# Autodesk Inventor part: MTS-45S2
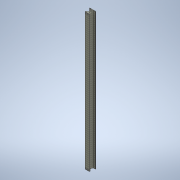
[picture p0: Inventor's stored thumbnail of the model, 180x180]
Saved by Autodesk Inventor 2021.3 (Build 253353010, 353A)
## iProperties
Created: 2021-11
Part Number: MTS-45S2
Material: Concrete, Precast
Document SubType Name: Modeling
Designer: u1426
Density: 2.40731 g/cm^3
Appearance: Smooth Precast Structural
Author: u1426
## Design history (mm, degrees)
sketch "Sketch1"
  geometry: L1 (0, 0)-(-400.05, 0); L2 (-431.8, -31.75)-(-431.8, -143.319); L3 (-390.596, -202.776)-(-208.052, -271.231); L4 (-76.2, -461.493)-(-76.2, -849.936); L5 (-267.326, -1052.777)-(-573.764, -1071.017); L6 (-609.6, -1109.05)-(-609.6, -1143); L7 (0, 0)-(400.05, 0); L8 (431.8, -31.75)-(431.8, -143.319); L9 (390.596, -202.776)-(208.052, -271.231); L10 (76.2, -461.493)-(76.2, -849.936); L11 (267.326, -1052.777)-(573.764, -1071.017); L12 (609.6, -1109.05)-(609.6, -1143); L13 (609.6, -1143)-(-609.6, -1143); L14 (431.8, -31.75)-(400.05, 0); L15 (-400.05, 0)-(-431.8, -31.75); A1 r 38.1 centre (571.5, -1109.05) between (609.6, -1109.05) and (573.764, -1071.017); A2 r 38.1 centre (-571.5, -1109.05) between (-573.764, -1071.017) and (-609.6, -1109.05); A3 r 203.2 centre (-279.4, -849.936) between (-267.326, -1052.777) and (-76.2, -849.936); A4 r 203.2 centre (279.4, -849.936) between (76.2, -849.936) and (267.326, -1052.777); A5 r 203.2 centre (279.4, -461.493) between (208.052, -271.231) and (76.2, -461.493); A6 r 203.2 centre (-279.4, -461.493) between (-76.2, -461.493) and (-208.052, -271.231); A7 r 63.5 centre (368.3, -143.319) between (390.596, -202.776) and (431.8, -143.319); A8 r 63.5 centre (-368.3, -143.319) between (-431.8, -143.319) and (-390.596, -202.776); 10 further points
  constraints: 30 end point, 20 point on line, 16 point on circle, 16 tangent, 8 centre point, 5 equal radius, 3 parallel, 3 perpendicular, 2 horizontal, 1 vertical
  dimensions: "d0" = 431.8 distance of L1.start point (-431.8, 0); "d1" = 187.325 distance of point (-431.8, 0) point (-431.8, -187.325); "d2" = 355.6 horizontal distance of point (-431.8, -187.325) point (-76.2, -320.675); "d3" = 133.35 vertical distance of point (-431.8, -187.325) point (-76.2, -320.675); "d4" = 31.75 vertical distance of point (-76.2, -1041.4) point (-609.6, -1073.15); "d5" = 69.85 distance of point (-609.6, -1073.15) L6.end; "d7" = 533.4 horizontal distance of point (-76.2, -1041.4) point (-609.6, -1073.15); "d8" = 431.8 distance of L1.start point (431.8, 0); "d9" = 187.325 distance of point (431.8, 0) point (431.8, -187.325); "d10" = 355.6 horizontal distance of point (431.8, -187.325) point (76.2, -320.675); "d11" = 133.35 vertical distance of point (431.8, -187.325) point (76.2, -320.675); "d12" = 533.4 horizontal distance of point (76.2, -1041.4) point (609.6, -1073.15); "d13" = 31.75 vertical distance of point (76.2, -1041.4) point (609.6, -1073.15); "d14" = 1143 distance between parallel lines of L1 L13; "d15" = 69.85 distance of point (609.6, -1073.15) L12.end; "d16" = 1219.2 distance between parallel lines of L6 L12 (derived); "d17" = 863.6 distance between parallel lines of L2 L8 (derived); "d18" = 152.4 distance between parallel lines of L4 L10 (derived); "d19" = 38.1 radius of A1; "d20" = 203.2 radius of A3; "d21" = 63.5 radius of A7; "d22" = 31.75 distance of L8.start point (431.8, 0); "d23" = 31.75 distance of L7.end point (431.8, 0) (= d22); "d24" = 31.75 distance of L1.end point (-431.8, 0) (= d22); "d25" = 31.75 distance of L2.start point (-431.8, 0) (= d24)
extrude "Extrusion1" new body sketch "Sketch1" distance "d26" = 28270.2; taper "d27" = 0 deg
sketch "Sketch4"
  geometry: L1 (-31.75, 28270.2)-(-31.75, 0) reference; L2 (-31.75, 28155.9)-(-6.35, 28155.9); L3 (-6.35, 28155.9)-(-6.35, 28003.5); L4 (-6.35, 28003.5)-(-31.75, 28003.5); L5 (-31.75, 28003.5)-(-31.75, 28155.9); L6 (-31.75, 114.3)-(-6.35, 114.3); L7 (-6.35, 114.3)-(-6.35, 266.7); L8 (-6.35, 266.7)-(-31.75, 266.7); L9 (-31.75, 266.7)-(-31.75, 114.3); L10 (0, 0)-(-31.75, 0) reference; L11 (-31.75, 28270.2)-(0, 28270.2) reference; 3 further points
  constraints: 16 end point, 4 parallel, 3 point on line, 2 horizontal, 2 perpendicular
  dimensions: "d40" = 25.4 distance of L3.end L4.end; "d41" = 152.4 distance of L2.end L3.end; "d42" = 152.4 distance of L7.end L6.end; "d43" = 114.3 distance between parallel lines of L6 L10; "d44" = 114.3 distance between parallel lines of L2 L11
extrude "Extrusion3" cut sketch "Sketch4" extent not by distance; stored distance "d45" = 0; taper "d46" = 0 deg
sketch "Sketch5"
  geometry: L1 (850.9, 0)-(0, 0) reference; L2 (0, 0)-(850.9, 0); L3 (825.5, -25.4)-(857.25, 6.35) reference; L4 (25.4, -25.4)-(825.5, -25.4) reference; L5 (-6.35, 6.35)-(25.4, -25.4) reference; 1 further point
  constraints: 2 end point, 1 horizontal, 1 point on line
extrude "Extrusion4" new body sketch "Sketch5" distance "d47" = 152.4; taper "d48" = 0 deg
sketch "Sketch6"
  geometry: L1 (25.4, -25.4)-(0, 0) reference; L2 (825.5, -25.4)-(25.4, -25.4) reference; L3 (850.9, 0)-(825.5, -25.4) reference; L4 (850.9, 0)-(0, 0); 2 further points
  constraints: 2 end point, 1 horizontal, 1 point on line
extrude "Extrusion5" new body sketch "Sketch6" distance "d49" = 152.4; taper "d50" = 0 deg
body "Solid1"
body "Solid2"
body "Solid3"
